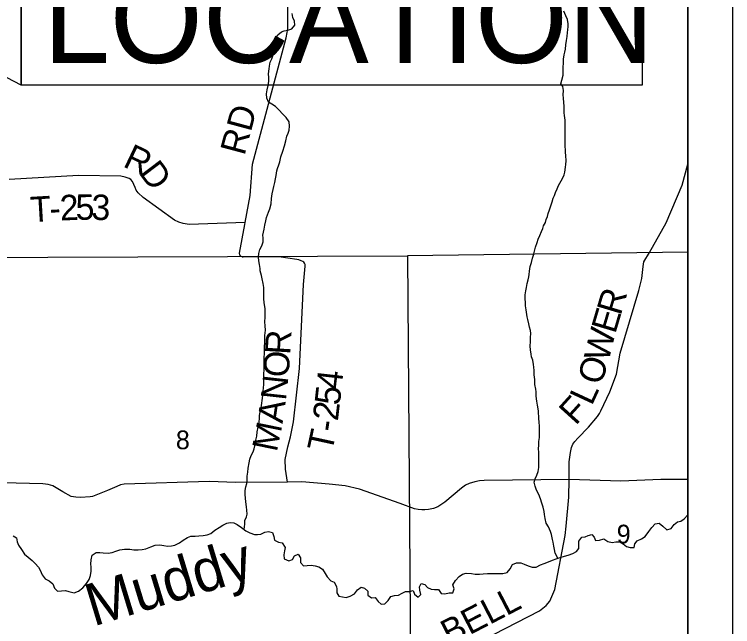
# Model space of a CAD drawing. Extents: x 0 to 34, y 0 to 22.
# Drawn here: x 7.392 to 9, y 15.175 to 16.545 of the extents above; entities that cross this region are included whole.
import ezdxf

# ---------------------------------------------------------------- set-up
doc = ezdxf.new("R2010")
doc.units = 0
for name, color, linetype in [('Default', 7, 'Continuous'), ('SH_Cut_Line', 7, 'Continuous'), ('SH_Data', 7, 'Continuous'), ('SH_Text', 7, 'Continuous')]:
    doc.layers.add(name, color=color, linetype=linetype)

msp = doc.modelspace()

# ---------------------------------------------------------------- linework, layer by layer
at = {"layer": 'Default'}
for points in [[(6.2892, 14.1), (8.9, 14.1), (8.9, 17.02), (8.2009, 17.0196), (7.211, 17.0191), (7.2045, 17.0191), (6.9328, 17.0189), (6.927, 17.0189), (6.6903, 17.0144), (6.3876, 17.0173), (6.3215, 17.0189), (6.2871, 17.0188), (6.2922, 16.0152), (6.2959, 15.2705), (6.2926, 14.8972), (6.2889, 14.4906), (6.2892, 14.18)], [(8.9, 15.006), (8.9, 16.013), (8.2726, 16.0048), (8.2795, 14.9973)], [(8.2726, 16.0048), (8.2795, 14.9973), (7.2656, 14.9873), (7.265, 16.0012)]]:
    msp.add_lwpolyline(points, close=True, dxfattribs=at)
for points in [[(8.0035, 15.4988), (7.999, 15.5279), (7.9988, 15.5496), (8.0045, 15.5774), (8.0108, 15.5999), (8.0173, 15.6338), (8.0308, 15.7527), (8.0398, 15.9411), (8.0435, 15.9822), (8.043, 15.9854), (8.0419, 15.9883), (8.0402, 15.9907), (8.0381, 15.9924), (8.034, 15.9942), (8.0292, 15.996), (8.0243, 15.9972), (7.9843, 16.0025), (7.9043, 16.0022), (7.9032, 16.0024), (7.9019, 16.0027), (7.9001, 16.0034), (7.8991, 16.0041), (7.8982, 16.0051), (7.8974, 16.0063), (7.8968, 16.0079), (7.8966, 16.0095), (7.8966, 16.0112), (7.9081, 16.0748), (7.9089, 16.0793), (7.92, 16.14), (7.9257, 16.21), (8.0006, 16.4927), (8.0031, 16.505), (8.0043, 16.5136), (8.0043, 16.5204), (8.0042, 16.7594)], [(8.0074, 16.305), (8.0008, 16.3144), (7.9927, 16.3226), (7.985, 16.3309), (7.9769, 16.3395), (7.9689, 16.3443), (7.9612, 16.3488), (7.9573, 16.3578), (7.9568, 16.3673), (7.9582, 16.3764), (7.9607, 16.386), (7.9621, 16.3962), (7.9619, 16.4042), (7.9611, 16.4126), (7.9628, 16.4236), (7.9631, 16.4293), (7.9649, 16.438), (7.9685, 16.4461), (7.9715, 16.4545), (7.9732, 16.464), (7.9757, 16.4739), (7.9764, 16.4826), (7.9774, 16.4914), (7.9818, 16.4994), (7.9905, 16.5064), (7.9965, 16.5084), (8.0048, 16.51), (8.0135, 16.5132), (8.0199, 16.5208), (8.0197, 16.53), (8.0154, 16.5382), (8.0138, 16.547)], [(8.6229, 16.1862), (8.6247, 16.1919), (8.6261, 16.2033), (8.6267, 16.2091), (8.6274, 16.2174), (8.6264, 16.2292), (8.6256, 16.236), (8.6253, 16.2557), (8.6255, 16.2652), (8.6255, 16.2709), (8.625, 16.2785), (8.6252, 16.288), (8.6249, 16.3085), (8.6236, 16.3191), (8.6232, 16.3248), (8.6231, 16.3305), (8.6229, 16.3396), (8.6224, 16.3483), (8.6212, 16.3578), (8.621, 16.365), (8.6217, 16.3753), (8.6196, 16.3836), (8.6158, 16.39), (8.6175, 16.3984), (8.6204, 16.4094), (8.6209, 16.4261), (8.6211, 16.4368), (8.6218, 16.4451), (8.6228, 16.455), (8.6242, 16.4607), (8.6256, 16.4676), (8.6266, 16.4771), (8.628, 16.487), (8.6294, 16.4957), (8.6304, 16.5049), (8.6311, 16.5106), (8.6321, 16.5182), (8.632, 16.5239), (8.6304, 16.5337), (8.6268, 16.5424), (8.6221, 16.5522)], [(7.9067, 15.3926), (7.9081, 15.4048), (7.9083, 15.4128), (7.9116, 15.4212), (7.9131, 15.4269), (7.9129, 15.4356), (7.9121, 15.4436), (7.9104, 15.4546), (7.9099, 15.4629), (7.909, 15.4709), (7.9093, 15.48), (7.9107, 15.488), (7.9124, 15.4956), (7.9135, 15.5032), (7.9137, 15.512), (7.9147, 15.5211), (7.9157, 15.5302), (7.9182, 15.5417), (7.9193, 15.5497), (7.9226, 15.558), (7.927, 15.5668), (7.9292, 15.5733), (7.9313, 15.5829), (7.9331, 15.5928), (7.9348, 15.6019), (7.9355, 15.611), (7.938, 15.6217), (7.9401, 15.6327), (7.9411, 15.6419), (7.9414, 15.6479), (7.9428, 15.6556), (7.9446, 15.6647), (7.9463, 15.6753), (7.947, 15.6814), (7.9483, 15.6928), (7.949, 15.702), (7.9506, 15.7172), (7.9504, 15.7316), (7.9507, 15.7403), (7.9517, 15.751), (7.9516, 15.7571), (7.9518, 15.7692), (7.9517, 15.7776), (7.9519, 15.7867), (7.9522, 15.7954), (7.952, 15.8034), (7.9527, 15.8091), (7.9529, 15.8197), (7.9532, 15.827), (7.9546, 15.8384), (7.954, 15.8486), (7.9532, 15.8573), (7.9538, 15.868), (7.9535, 15.887), (7.9518, 15.9002), (7.9509, 15.9093), (7.9508, 15.9173), (7.951, 15.9256), (7.9509, 15.9344), (7.9496, 15.9431), (7.9468, 15.9537), (7.9452, 15.9609), (7.9428, 15.9711), (7.9423, 15.9768), (7.9407, 15.9855), (7.9394, 15.9935), (7.9385, 16.0022), (7.9395, 16.0102), (7.9417, 16.0193), (7.9461, 16.0273), (7.949, 16.0361), (7.9489, 16.0452), (7.9488, 16.0513), (7.9499, 16.0578), (7.9513, 16.0646), (7.9527, 16.0734), (7.9552, 16.0837), (7.957, 16.0909), (7.9614, 16.1027), (7.9643, 16.11), (7.9672, 16.1214), (7.9681, 16.1336), (7.9691, 16.1435), (7.9713, 16.1534), (7.9735, 16.1602), (7.9756, 16.169), (7.977, 16.1774), (7.978, 16.185), (7.9802, 16.1949), (7.9812, 16.2006), (7.9841, 16.209), (7.9863, 16.2155), (7.9888, 16.2269), (7.9932, 16.2395), (7.9968, 16.2509), (7.9997, 16.262), (8.0026, 16.2727), (8.0055, 16.2792), (8.0077, 16.2864), (8.0083, 16.2955), (8.0074, 16.305)], [(8.6338, 15.5043), (8.6343, 15.5443), (8.6372, 15.5649), (8.6397, 15.5764), (8.6427, 15.5836), (8.6471, 15.5899), (8.6532, 15.5974), (8.6777, 15.622), (8.6978, 15.6458), (8.7021, 15.6519), (8.7051, 15.6581), (8.7248, 15.7008), (8.74, 15.7405), (8.7482, 15.787), (8.7897, 15.9275), (8.7966, 15.9542), (8.7998, 15.9812), (8.8016, 15.9915), (8.8143, 16.0126), (8.8516, 16.0788), (8.8869, 16.1632), (8.9, 16.2103)], [(7.9089, 16.0793), (7.784, 16.0754), (7.7699, 16.0772), (7.7607, 16.0801), (7.7507, 16.085), (7.6805, 16.1356), (7.6698, 16.146), (7.6653, 16.1523), (7.6627, 16.1579), (7.6571, 16.171), (7.6534, 16.1755), (7.6496, 16.1779), (7.6403, 16.1811), (7.6309, 16.1831), (7.536, 16.1851), (7.3811, 16.1756)], [(8.609, 15.3282), (8.6029, 15.3399), (8.6012, 15.3482), (8.5996, 15.3554), (8.5983, 15.3642), (8.5967, 15.3706), (8.5943, 15.3816), (8.5923, 15.3884), (8.5879, 15.3989), (8.5825, 15.4072), (8.5801, 15.4171), (8.5792, 15.4262), (8.5783, 15.4326), (8.5759, 15.4424), (8.5731, 15.4519), (8.5703, 15.4614), (8.566, 15.4708), (8.5609, 15.4806), (8.5582, 15.4897), (8.5561, 15.4984), (8.5583, 15.5064), (8.562, 15.5144), (8.5649, 15.5228), (8.5659, 15.5315), (8.5662, 15.5403), (8.566, 15.549), (8.5663, 15.5551), (8.5662, 15.5646), (8.5657, 15.5744), (8.566, 15.5801), (8.5662, 15.5893), (8.5676, 15.5988), (8.5678, 15.6079), (8.5676, 15.6235), (8.5667, 15.6333), (8.5662, 15.6402), (8.5661, 15.6462), (8.5657, 15.6523), (8.5652, 15.658), (8.5635, 15.6712), (8.5615, 15.68), (8.5606, 15.6913), (8.56, 15.7004), (8.5592, 15.7069), (8.5575, 15.7175), (8.557, 15.7281), (8.5557, 15.7387), (8.5555, 15.7486), (8.5547, 15.7562), (8.5542, 15.7619), (8.5526, 15.7713), (8.5498, 15.7793), (8.5489, 15.7853), (8.5473, 15.7948), (8.5472, 15.8032), (8.5474, 15.813), (8.5476, 15.8225), (8.5483, 15.8313), (8.5478, 15.8377), (8.5454, 15.8457), (8.5438, 15.8532), (8.5414, 15.8623), (8.5401, 15.8687), (8.538, 15.8839), (8.5367, 15.8934), (8.5363, 15.8998), (8.5357, 15.9093), (8.536, 15.9177), (8.537, 15.9264), (8.5384, 15.934), (8.5402, 15.9428), (8.5424, 15.9516), (8.5438, 15.9577), (8.5445, 15.9634), (8.5455, 15.9706), (8.5472, 15.9809), (8.5498, 15.9904), (8.5523, 15.9995), (8.5541, 16.0068), (8.5573, 16.0182), (8.5588, 16.0243), (8.5624, 16.0346), (8.565, 16.0426), (8.5683, 16.0506), (8.5719, 16.0598), (8.5749, 16.0663), (8.5767, 16.072), (8.5815, 16.0797), (8.5829, 16.0862), (8.5859, 16.0934), (8.5873, 16.0995), (8.5902, 16.1079), (8.5935, 16.119), (8.596, 16.1258), (8.5986, 16.1339), (8.6011, 16.14), (8.6037, 16.1468), (8.607, 16.1552), (8.6099, 16.1625), (8.6192, 16.1778), (8.6229, 16.1862)], [(8.6338, 15.5043), (8.444, 15.5025), (8.4338, 15.5015), (8.4231, 15.4995), (8.4106, 15.4956), (8.4018, 15.4916), (8.3928, 15.4855), (8.3555, 15.4539), (8.3403, 15.4435), (8.3302, 15.4394), (8.3195, 15.4372), (8.3109, 15.4365), (8.3044, 15.437), (8.296, 15.4375), (8.2878, 15.4391), (8.2561, 15.451), (8.1651, 15.4828), (8.1331, 15.4904), (8.0968, 15.4939), (8.0359, 15.499), (8.0035, 15.4988), (7.8878, 15.4982), (7.8287, 15.5003), (7.638, 15.4945), (7.6299, 15.4926), (7.6221, 15.489), (7.6012, 15.4801), (7.5671, 15.4669), (7.5622, 15.4656), (7.5401, 15.4642), (7.5301, 15.4647), (7.5199, 15.4667), (7.5011, 15.4771), (7.4785, 15.4906), (7.4679, 15.4936), (7.4564, 15.4949), (7.3962, 15.4962), (6.8451, 15.506)], [(8.2961, 15.0329), (8.3038, 15.0449), (8.3142, 15.0588), (8.333, 15.0804), (8.3646, 15.1066), (8.5675, 15.2107), (8.5826, 15.2226), (8.5909, 15.2326), (8.6017, 15.2586), (8.6251, 15.3794), (8.6275, 15.4004), (8.6333, 15.4648), (8.6338, 15.5043)], [(8.9, 15.5042), (8.8392, 15.5045), (8.7494, 15.5006), (8.6338, 15.5043)], [(8.5257, 15.3179), (8.5337, 15.315), (8.5421, 15.3117), (8.5513, 15.3084), (8.56, 15.3082), (8.5698, 15.3136), (8.5785, 15.3168), (8.5879, 15.3203), (8.597, 15.3239), (8.6049, 15.3267), (8.614, 15.3302), (8.6235, 15.3334), (8.6322, 15.3354), (8.6424, 15.339), (8.6503, 15.3432), (8.6555, 15.3502), (8.6561, 15.3585), (8.6556, 15.3669), (8.6623, 15.3757), (8.6703, 15.3766), (8.6763, 15.3793), (8.6847, 15.3817), (8.6901, 15.3753), (8.6928, 15.3678), (8.7019, 15.369), (8.7118, 15.3718), (8.7206, 15.3659), (8.7301, 15.3638), (8.7384, 15.365), (8.7472, 15.3651), (8.7548, 15.3603), (8.7621, 15.3547), (8.7709, 15.3522), (8.7793, 15.3523), (8.7814, 15.3603), (8.7866, 15.3676), (8.7957, 15.3715), (8.8044, 15.377), (8.8122, 15.3881), (8.8189, 15.3973), (8.8264, 15.4054), (8.8355, 15.4067), (8.8435, 15.3999), (8.8528, 15.3917), (8.8626, 15.3953), (8.8689, 15.4041), (8.8764, 15.4099), (8.8844, 15.4112), (8.8915, 15.4166), (8.8997, 15.4258), (8.9, 15.4259)], [(7.8508, 15.3968), (7.8591, 15.4022), (7.8678, 15.4065), (7.8757, 15.4085), (7.8833, 15.4079), (7.8914, 15.4038), (7.9009, 15.3975), (7.9102, 15.3896), (7.9194, 15.3852), (7.93, 15.3816), (7.9365, 15.3813), (7.9441, 15.3825), (7.9531, 15.3865), (7.9611, 15.3885), (7.9699, 15.3863), (7.9734, 15.3773), (7.975, 15.3685), (7.9838, 15.3641), (7.9915, 15.3631), (7.9984, 15.3525), (7.997, 15.3449), (7.9953, 15.3358), (7.9965, 15.3267), (8.0065, 15.3227), (8.0148, 15.3254), (8.0196, 15.3339), (8.0275, 15.3374), (8.033, 15.3291), (8.0331, 15.3192), (8.0393, 15.3114), (8.0476, 15.3122), (8.0564, 15.3131), (8.0655, 15.3114), (8.0735, 15.3088), (8.0823, 15.304), (8.0878, 15.2946), (8.0928, 15.2867), (8.1005, 15.2777), (8.1082, 15.2751), (8.1133, 15.2649), (8.1141, 15.2589), (8.1142, 15.2513), (8.1189, 15.2434), (8.1269, 15.2423), (8.1349, 15.2402), (8.1443, 15.2434), (8.1534, 15.2484), (8.1601, 15.258), (8.1687, 15.2638), (8.1764, 15.2613), (8.1837, 15.2549), (8.1838, 15.2458), (8.1915, 15.2399), (8.2002, 15.2404), (8.2064, 15.2313), (8.213, 15.2253), (8.2217, 15.2266), (8.2288, 15.2335), (8.2351, 15.2431), (8.2434, 15.2448), (8.2525, 15.2457), (8.2605, 15.25), (8.268, 15.2539), (8.2771, 15.254), (8.285, 15.256), (8.2882, 15.2477), (8.2963, 15.2413), (8.3023, 15.2475), (8.3002, 15.257), (8.2994, 15.2646), (8.3031, 15.2718), (8.3114, 15.27), (8.3169, 15.2629), (8.3253, 15.2589), (8.3329, 15.2586), (8.3416, 15.2587), (8.3478, 15.2493), (8.3558, 15.249), (8.3656, 15.2507), (8.374, 15.2508), (8.3769, 15.2603), (8.3741, 15.269), (8.38, 15.2786), (8.3879, 15.2875), (8.3954, 15.2925), (8.4037, 15.2953), (8.4155, 15.2943), (8.4235, 15.2925), (8.4334, 15.2931), (8.4417, 15.2936), (8.4512, 15.2941), (8.4569, 15.2942), (8.4626, 15.2939), (8.4687, 15.2943), (8.4774, 15.2944), (8.4858, 15.2942), (8.4952, 15.2962), (8.502, 15.305), (8.5075, 15.3142), (8.5162, 15.3182), (8.5257, 15.3179)], [(7.39, 15.3788), (7.3973, 15.374), (7.3986, 15.3653), (7.4017, 15.3577), (7.4083, 15.3479), (7.4153, 15.3378), (7.4234, 15.3307), (7.4319, 15.3236), (7.4392, 15.3169), (7.4461, 15.3082), (7.4504, 15.3018), (7.4547, 15.2916), (7.4613, 15.2826), (7.4705, 15.2778), (7.4786, 15.2711), (7.4825, 15.2617), (7.4891, 15.2549), (7.4982, 15.2554), (7.5065, 15.2563), (7.5145, 15.2541), (7.5263, 15.2513), (7.5358, 15.2544), (7.5455, 15.2622), (7.5541, 15.2722), (7.5597, 15.281), (7.563, 15.2898), (7.564, 15.2993), (7.5642, 15.3088), (7.5638, 15.3148), (7.5644, 15.3251), (7.5669, 15.335), (7.5755, 15.3412), (7.5835, 15.3409), (7.5911, 15.3403), (7.6025, 15.3401), (7.6116, 15.341), (7.6195, 15.3441), (7.6282, 15.3473), (7.6388, 15.3489), (7.651, 15.3487), (7.6601, 15.3473), (7.6693, 15.3471), (7.6784, 15.3476), (7.6867, 15.3492), (7.6976, 15.354), (7.7078, 15.3575), (7.7177, 15.3584), (7.7268, 15.3567), (7.7348, 15.3556), (7.7443, 15.3558), (7.7519, 15.3574), (7.7621, 15.3629), (7.77, 15.369), (7.7801, 15.3749), (7.7877, 15.3776), (7.7972, 15.3778), (7.8055, 15.3787), (7.815, 15.3796), (7.8241, 15.3808), (7.8324, 15.384), (7.8414, 15.3913), (7.8508, 15.3968)]]:
    msp.add_lwpolyline(points, dxfattribs=at)
at = {"layer": 'SH_Cut_Line'}
msp.add_lwpolyline([(2.1, 17.0156), (2.1, 14.1), (8.9, 14.1), (8.9, 17.02)], dxfattribs=at)
at = {"layer": 'SH_Data'}
for p, q in [((9, 21), (9, 14)), ((8.9, 20.9), (8.9, 14.1))]:
    msp.add_line(p, q, dxfattribs=at)
at = {"layer": 'SH_Text'}
for points in [[(5.6822, 17.291), (7.4073, 16.9867), (7.4073, 16.3867)], [(7.4073, 16.9867), (8.7975, 16.9867), (8.7975, 16.3867), (7.4073, 16.3867)], [(7.4073, 16.9867), (8.7975, 16.9867), (8.7975, 16.3867), (7.4073, 16.3867)]]:
    msp.add_lwpolyline(points, close=True, dxfattribs=at)

# ---------------------------------------------------------------- texts
at = {"layer": 'Default'}
for s, height, rotation, p in [('RD', 0.05682, 75.0054, (7.9073, 16.2276)), ('R', 0.0568, 334.6254, (7.6331, 16.2058)), ('D', 0.0568, 307.1475, (7.6698, 16.1903)), ('2', 0.0568, 2.4622, (7.4952, 16.0839)), ('5', 0.0568, 0.687, (7.5297, 16.0854)), ('3', 0.0568, 358.5323, (7.5642, 16.0858)), ('T', 0.0568, 3.3705, (7.4297, 16.0801)), ('-', 0.0568, 3.1629, (7.4721, 16.0826)), ('R', 0.0568, 73.4439, (8.7493, 15.8696)), ('E', 0.0568, 73.4777, (8.7372, 15.8288)), ('R', 0.0568, 86.6416, (8.0098, 15.7828)), ('W', 0.0568, 76.3146, (8.7219, 15.7656)), ('O', 0.0568, 85.2946, (8.0056, 15.7315)), ('O', 0.0568, 72.1209, (8.7053, 15.7136)), ('4', 0.0568, 83.5282, (8.1243, 15.7038)), ('N', 0.0568, 83.734, (8, 15.6801)), ('5', 0.0568, 83.6183, (8.1205, 15.6691)), ('L', 0.0568, 65.1288, (8.6846, 15.668)), ('F', 0.0568, 47.8334, (8.6486, 15.624)), ('A', 0.0568, 81.8416, (7.9926, 15.6286)), ('2', 0.0568, 83.4177, (8.1164, 15.6341)), ('M', 0.0568, 78.4624, (7.9797, 15.5645)), ('-', 0.0568, 81.7729, (8.1129, 15.6092)), ('8', 0.0419, 0, (7.7539, 15.5723)), ('T', 0.0568, 77.705, (8.103, 15.5634)), ('9', 0.0419, 0, (8.7406, 15.3615)), ('Muddy', 0.09472, 16.914, (7.5692, 15.1754)), ('BELL', 0.05682, 27.4256, (8.3661, 15.1325))]:
    msp.add_text(s, height=height, rotation=rotation, dxfattribs=at).set_placement(p)
at = {"layer": 'SH_Text'}
msp.add_text('LOCATION', height=0.2, dxfattribs=at).set_placement((7.4573, 16.4367))

doc.saveas('drawing.dxf')
